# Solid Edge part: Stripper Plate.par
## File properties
Author: Dan
Template: metric part.par
Last saved by: Dan
Revision: 24
Application: Solid Edge
Density: 7833.000 kg/m^3
Accuracy: 0.990
Material: Steel
Face Style: Steel
Fill Style: ANSI32(Steel)
Virtual Style: Machined steel
Coef. of Thermal Exp: 1.3e-05
Thermal Conductivity: 32.0
Specific Heat: 481.0
Modulus of Elasticity: 199947953000.0
Poisson's Ratio: 0.29
Yield Stress: 262000766.0
Ultimate Stress: 358527364.0
Elongation: 0.0
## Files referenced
..\Fixed Half.asm
C:\Drawing Files Other\Dave\Tente\HUP 125X36H45-TSA 02-07-2011\Wheel Mould\FH Clamping Plate.par
C:\Drawing Files Other\Dave\Tente\HUP 125X36H45-TSA 02-07-2011\Wheel Mould\Runner Plate.par
YC:\Drawing Files Other\Dave\Tente\HUP 125X36H45-TSA 02-07-2011\Wheel Mould\Fixed Half.asm
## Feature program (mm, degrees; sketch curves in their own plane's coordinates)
sketch for "unnamed Protrusion 1" plane through (0, 0, 0) normal (0, 0, 1) x-axis (1, 0, 0)
extrude "unnamed Protrusion 1" add finite 26 along -normal
sketch for "Hole_9" plane through (-12.9045, 10.6284, -26) normal (0, 0, -1) x-axis (-1, 0, 0)
hole "Hole_9" diameter 42 through  CounterBoreDepth = 6 mm; VBottomAngle = 118 deg
sketch for "unnamed Hole 1" plane through (-12.9045, 10.6284, -26) normal (0, 0, -1) x-axis (-1, 0, 0)
hole "unnamed Hole 1" through
sketch for "unnamed Hole 2" plane through (-12.9045, 10.6284, -26) normal (0, 0, -1) x-axis (-1, 0, 0)
hole "unnamed Hole 2" through
sketch for "unnamed Hole 3" plane through (-12.9045, 10.6284, -26) normal (0, 0, -1) x-axis (-1, 0, 0)
  hole centre (157.0955, -180.6284) bore radius 21
hole "unnamed Hole 3" through
pattern "unnamed Pattern 1" of "Hole_9", "unnamed Hole 1", "unnamed Hole 2", "unnamed Hole 3"
sketch for "Hole_13" plane through (0, 0, 0) normal (0, 0, 1) x-axis (-1, 0, 0)
hole "Hole_13" diameter 10 finite  VBottomAngle = 118 deg
sketch for "unnamed Hole 4" plane through (0, 0, 0) normal (0, 0, 1) x-axis (-1, 0, 0)
hole "unnamed Hole 4" finite
sketch for "unnamed Hole 5" plane through (0, 0, 0) normal (0, 0, 1) x-axis (-1, 0, 0)
  hole centre (170, 106) bore radius 4.188
hole "unnamed Hole 5" finite
sketch for "unnamed Hole 6" plane through (0, 0, 0) normal (0, 0, 1) x-axis (-1, 0, 0)
  hole centre (170, -106) bore radius 4.188
hole "unnamed Hole 6" finite
pattern "unnamed Pattern 2" of "Hole_13", "unnamed Hole 4", "unnamed Hole 5", "unnamed Hole 6"
sketch for "Hole_17" plane through (0, 0, -26) normal (0, 0, -1) x-axis (1, 0, 0)
hole "Hole_17" diameter 10 finite  VBottomAngle = 118 deg
sketch for "unnamed Hole 7" plane through (0, 0, -26) normal (0, 0, -1) x-axis (1, 0, 0)
hole "unnamed Hole 7" finite
sketch for "unnamed Hole 8" plane through (0, 0, -26) normal (0, 0, -1) x-axis (1, 0, 0)
  hole centre (120, 170) bore radius 4.188
hole "unnamed Hole 8" finite
sketch for "unnamed Hole 9" plane through (0, 0, -26) normal (0, 0, -1) x-axis (1, 0, 0)
  hole centre (120, -170) bore radius 4.188
hole "unnamed Hole 9" finite
pattern "unnamed Pattern 3" of "Hole_17", "unnamed Hole 7", "unnamed Hole 8", "unnamed Hole 9"
sketch for "Hole_21" plane through (0, 0, -26) normal (0, 0, -1) x-axis (1, 0, 0)
  hole centre (-109.2946, 109.2947) bore radius 2.5
hole "Hole_21" diameter 5 through  VBottomAngle = 118 deg
sketch for "unnamed Hole 10" plane through (0, 0, -26) normal (0, 0, -1) x-axis (1, 0, 0)
  hole centre (-95.5061, 95.5061) bore radius 2.5
hole "unnamed Hole 10" through
sketch for "unnamed Hole 11" plane through (0, 0, -26) normal (0, 0, -1) x-axis (1, 0, 0)
  hole centre (-54.4939, 95.5061) bore radius 2.5
hole "unnamed Hole 11" through
sketch for "unnamed Hole 12" plane through (0, 0, -26) normal (0, 0, -1) x-axis (1, 0, 0)
  hole centre (-40.7053, 109.2946) bore radius 2.5
hole "unnamed Hole 12" through
sketch for "unnamed Hole 13" plane through (0, 0, -26) normal (0, 0, -1) x-axis (1, 0, 0)
  hole centre (-54.4939, 54.4939) bore radius 2.5
hole "unnamed Hole 13" through
sketch for "unnamed Hole 14" plane through (0, 0, -26) normal (0, 0, -1) x-axis (1, 0, 0)
  hole centre (-40.7054, 40.7053) bore radius 2.5
hole "unnamed Hole 14" through
sketch for "unnamed Hole 15" plane through (0, 0, -26) normal (0, 0, -1) x-axis (1, 0, 0)
  hole centre (-95.5061, 54.4939) bore radius 2.5
hole "unnamed Hole 15" through
sketch for "unnamed Hole 16" plane through (0, 0, -26) normal (0, 0, -1) x-axis (1, 0, 0)
  hole centre (-109.2947, 40.7054) bore radius 2.5
hole "unnamed Hole 16" through
pattern "unnamed Pattern 4" of "Hole_21", "unnamed Hole 10", "unnamed Hole 11", "unnamed Hole 12", "unnamed Hole 13", "unnamed Hole 14", "unnamed Hole 15", "unnamed Hole 16"
mirror "unnamed Mirror 1" of "unnamed Pattern 4"
pattern "unnamed Pattern 5"
mirror "unnamed Mirror 2" of "unnamed Pattern 4", "unnamed Pattern 5"
pattern "unnamed Pattern 6"
sketch for "ExtrudedCutout_2" plane through (0, 0, 0) normal (0, 0, 1) x-axis (1, 0, 0)
  circle centre (0, 0) radius 42.5
extrude "ExtrudedCutout_2" cut finite 7 along -normal
sketch for "unnamed Cutout 1" plane through (0, 0, -7) normal (0, 0, 1) x-axis (1, 0, 0)
  circle centre (0, 0) radius 25
extrude "unnamed Cutout 1" cut through along -normal
sketch for "Hole_29" plane through (0, 0, -7) normal (0, 0, 1) x-axis (1, 0, 0)
  hole centre (0, 36) bore radius 2.4585
hole "Hole_29" nominal diameter 6 finite  VBottomAngle = 118 deg
sketch for "unnamed Hole 17" plane through (0, 0, -7) normal (0, 0, 1) x-axis (1, 0, 0)
  hole centre (-36, 0) bore radius 2.4585
hole "unnamed Hole 17" finite
sketch for "unnamed Hole 18" plane through (0, 0, -7) normal (0, 0, 1) x-axis (1, 0, 0)
  hole centre (0, -36) bore radius 2.4585
hole "unnamed Hole 18" finite
sketch for "unnamed Hole 19" plane through (0, 0, -7) normal (0, 0, 1) x-axis (1, 0, 0)
  hole centre (36, 0) bore radius 2.4585
hole "unnamed Hole 19" finite
pattern "unnamed Pattern 7" of "Hole_29", "unnamed Hole 17", "unnamed Hole 18", "unnamed Hole 19"
chamfer "Chamfer_1" setback 15
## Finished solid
Body 1: solid body, 78 faces, 121 edges, 8 vertices.
  Faces by surface: cylinder 54, cone 13, plane 11
  Edges by curve: circle 109, line 12
Bounding box of the edges (mm): 396.000 x 396.000 x 26.000, from (-198, -198, -26) to (198, 198, 0).
Cylindrical faces by radius (mm): R2.4585 x4, R2.5 x32, R4.188 x8, R21 x4, R23.5 x4, R25 x1, R42.5 x1
Conical faces (half-angle, radius in mm at the cone's reference point): 45 deg R25 x1, 59 deg R2.4585 x4, 59 deg R4.188 x8
Planar faces by outward normal: +x 1, +y 1, +z 2, -x 1, -y 1, -z 5
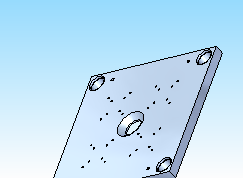
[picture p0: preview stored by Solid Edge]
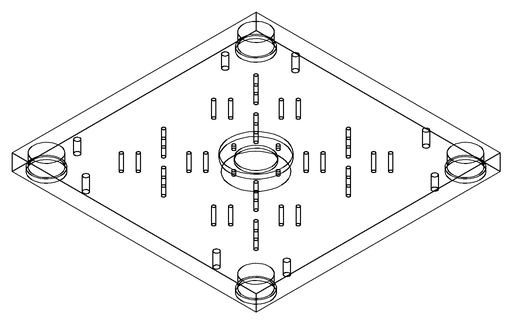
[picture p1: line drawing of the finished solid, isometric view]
